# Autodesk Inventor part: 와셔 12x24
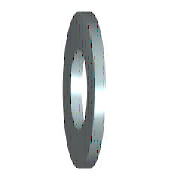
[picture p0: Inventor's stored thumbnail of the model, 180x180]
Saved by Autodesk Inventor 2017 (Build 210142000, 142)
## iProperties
IsCustomPart: 1
Created: 2012-02
Part Number: 와셔 12x24
Material: 스테인리스강
Description: 평면 와셔
Document SubType Name: Modeling
Standard: KS B 1326
Designer: mduedu
Standards Organization: KS
Language: ko-KR
Size Designation: 12x24
Categories: <MemberInstance><Categories><Category DisplayName="조임쇠" InternalName="e4da775c-781d-43d5-af7c-5136215cf5a6" Mnemonic="FSTN"><Category DisplayName="와셔" InternalN
Density: 1 g/cm^3
Appearance: Blue - Wall Paint - Glossy
Author: mduedu
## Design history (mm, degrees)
sketch "스케치"
  geometry: C1 r 12 at (0, 0); C2 r 6.5 at (0, 0); 1 further point
  constraints: 2 centre point, 2 coincident
  dimensions: "d0" = 13 diameter of C2 (= SD1); "d1" = 24 diameter of C1 (= SD2)
extrude "본체" new body sketch "스케치" distance "d2" = 2.5 (= SD); taper "d3" = 0 deg
workaxis "Work Axis1"
workplane "Work Plane1"
body "Solid1"
other parameters: "SD1" = 13 [user parameter; used in 1 equation term], "SD2" = 24 [user parameter; used in 1 equation term], "SD" = 2.5 [user parameter; used in 1 equation term], "d4" = 0, "d5" = 0, "d6" = 0, "d7" = 0, "NND" = 12 [user parameter]
